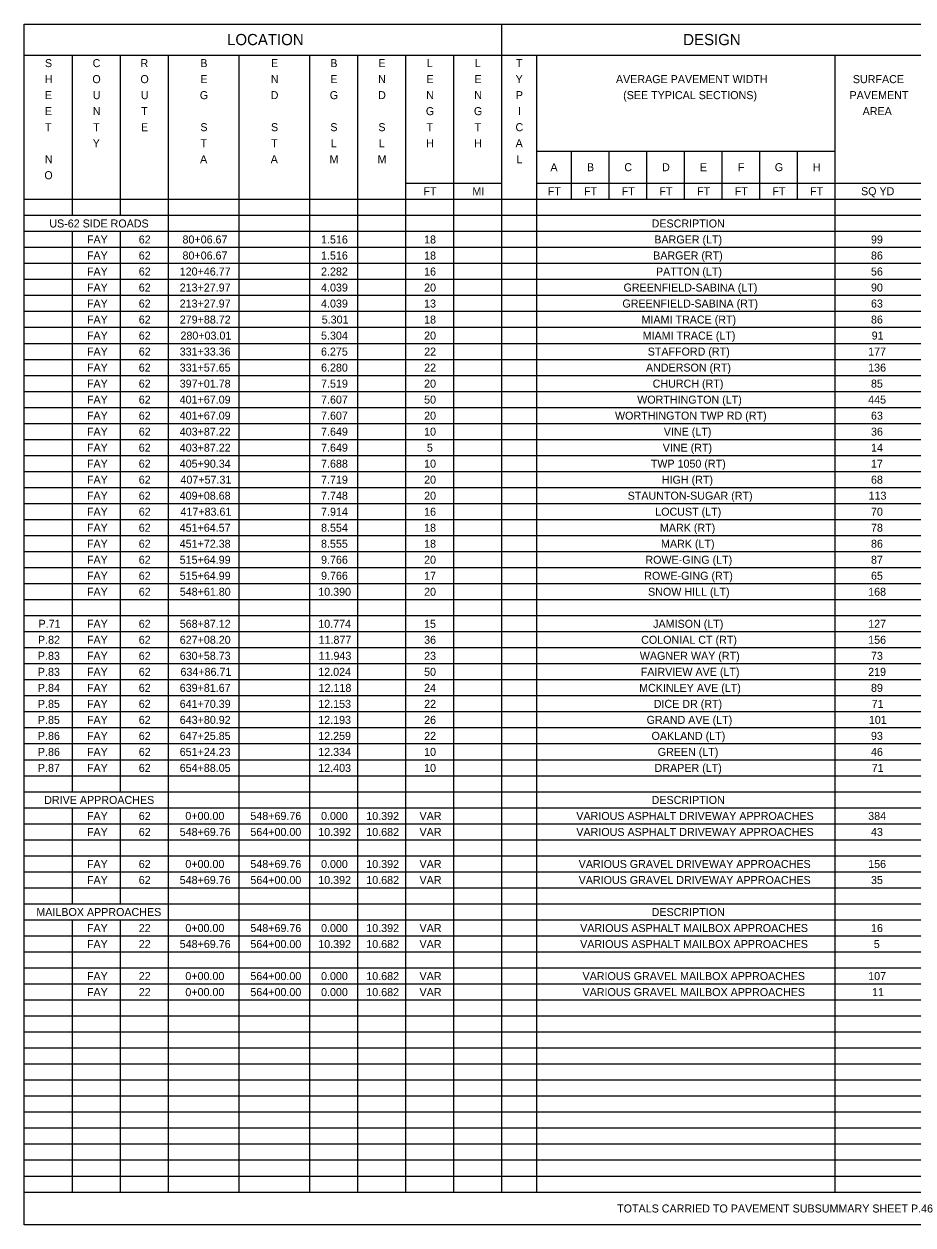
# Model space of a CAD drawing. Extents: x 12522 to 13018, y 1124 to 1902.
# Drawn here: x 12797.22 to 12812.77, y 1732.23 to 1753.23 of the extents above; entities that cross this region are included whole.
import ezdxf

# ---------------------------------------------------------------- set-up
doc = ezdxf.new("R2010")
doc.units = 0
for name, color, linetype in [('SC_Scratch1', 7, 'Continuous'), ('SH_Data', 7, 'Continuous'), ('SH_Text', 7, 'Continuous')]:
    doc.layers.add(name, color=color, linetype=linetype)

msp = doc.modelspace()

# ---------------------------------------------------------------- linework, layer by layer
at = {"layer": 'SC_Scratch1'}
msp.add_lwpolyline([(12797.224, 1753.227), (12827.724, 1753.227), (12827.724, 1732.227), (12797.224, 1732.227)], close=True, dxfattribs=at)
at = {"layer": 'SH_Data'}
for p, q in [((12805.575, 1753.227), (12805.575, 1732.803)), ((12797.224, 1752.683), (12827.678, 1752.683)), ((12798.064, 1752.683), (12798.064, 1749.883)), ((12798.904, 1752.683), (12798.904, 1749.883)), ((12799.744, 1752.683), (12799.744, 1732.803)), ((12800.979, 1752.683), (12800.979, 1732.803)), ((12802.215, 1752.683), (12802.215, 1732.803)), ((12803.055, 1752.683), (12803.055, 1732.803)), ((12803.895, 1752.683), (12803.895, 1732.803)), ((12804.735, 1752.683), (12804.735, 1732.803)), ((12806.184, 1752.683), (12806.184, 1732.803)), ((12811.405, 1752.683), (12811.405, 1732.803)), ((12806.184, 1751.003), (12811.405, 1751.003)), ((12806.794, 1751.003), (12806.794, 1750.163)), ((12807.452, 1751.003), (12807.452, 1750.163)), ((12808.111, 1751.003), (12808.111, 1750.163)), ((12808.77, 1751.003), (12808.77, 1750.163)), ((12809.429, 1751.003), (12809.429, 1750.163)), ((12810.088, 1751.003), (12810.088, 1750.163)), ((12810.747, 1751.003), (12810.747, 1750.163)), ((12803.895, 1750.443), (12805.575, 1750.443)), ((12806.184, 1750.443), (12827.678, 1750.443)), ((12797.224, 1750.163), (12827.678, 1750.163)), ((12797.224, 1749.883), (12827.678, 1749.883)), ((12797.224, 1749.603), (12827.678, 1749.603)), ((12798.064, 1749.603), (12798.064, 1739.803)), ((12798.904, 1749.603), (12798.904, 1739.803)), ((12797.224, 1749.323), (12827.678, 1749.323)), ((12797.224, 1749.043), (12827.678, 1749.043)), ((12797.224, 1748.763), (12827.678, 1748.763)), ((12797.224, 1748.483), (12827.678, 1748.483)), ((12797.224, 1748.203), (12827.678, 1748.203)), ((12797.224, 1747.923), (12827.678, 1747.923)), ((12797.224, 1747.643), (12827.678, 1747.643)), ((12797.224, 1747.363), (12827.678, 1747.363)), ((12797.224, 1747.083), (12827.678, 1747.083)), ((12797.224, 1746.803), (12827.678, 1746.803)), ((12797.224, 1746.523), (12827.678, 1746.523)), ((12797.224, 1746.243), (12827.678, 1746.243)), ((12797.224, 1745.963), (12827.678, 1745.963)), ((12797.224, 1745.683), (12827.678, 1745.683)), ((12797.224, 1745.403), (12827.678, 1745.403)), ((12797.224, 1745.123), (12827.678, 1745.123)), ((12797.224, 1744.843), (12827.678, 1744.843)), ((12797.224, 1744.563), (12827.678, 1744.563)), ((12797.224, 1744.283), (12827.678, 1744.283)), ((12797.224, 1744.003), (12827.678, 1744.003)), ((12797.224, 1743.723), (12827.678, 1743.723)), ((12797.224, 1743.443), (12827.678, 1743.443)), ((12797.224, 1743.163), (12827.678, 1743.163)), ((12797.224, 1742.883), (12827.678, 1742.883)), ((12797.224, 1742.603), (12827.678, 1742.603)), ((12797.224, 1742.323), (12827.678, 1742.323)), ((12797.224, 1742.043), (12827.678, 1742.043)), ((12797.224, 1741.763), (12827.678, 1741.763)), ((12797.224, 1741.483), (12827.678, 1741.483)), ((12797.224, 1741.203), (12827.678, 1741.203)), ((12797.224, 1740.923), (12827.678, 1740.923)), ((12797.224, 1740.643), (12827.678, 1740.643)), ((12797.224, 1740.363), (12827.678, 1740.363)), ((12797.224, 1740.083), (12827.678, 1740.083)), ((12797.224, 1739.803), (12827.678, 1739.803)), ((12797.224, 1739.523), (12827.678, 1739.523)), ((12798.064, 1739.523), (12798.064, 1737.843)), ((12798.904, 1739.523), (12798.904, 1737.843)), ((12797.224, 1739.243), (12827.678, 1739.243)), ((12797.224, 1738.963), (12827.678, 1738.963)), ((12797.224, 1738.683), (12827.678, 1738.683)), ((12797.224, 1738.403), (12827.678, 1738.403)), ((12797.224, 1738.123), (12827.678, 1738.123)), ((12797.224, 1737.843), (12827.678, 1737.843)), ((12797.224, 1737.563), (12827.678, 1737.563)), ((12798.064, 1737.563), (12798.064, 1732.803)), ((12798.904, 1737.563), (12798.904, 1732.803)), ((12797.224, 1737.283), (12827.678, 1737.283)), ((12797.224, 1737.003), (12827.678, 1737.003)), ((12797.224, 1736.723), (12827.678, 1736.723)), ((12797.224, 1736.443), (12827.678, 1736.443)), ((12797.224, 1736.163), (12827.678, 1736.163)), ((12797.224, 1735.883), (12827.678, 1735.883)), ((12797.224, 1735.603), (12827.678, 1735.603)), ((12797.224, 1735.323), (12827.678, 1735.323)), ((12797.224, 1735.043), (12827.678, 1735.043)), ((12797.224, 1734.763), (12827.678, 1734.763)), ((12797.224, 1734.483), (12827.678, 1734.483)), ((12797.224, 1734.203), (12827.678, 1734.203)), ((12797.224, 1733.923), (12827.678, 1733.923)), ((12797.224, 1733.643), (12827.678, 1733.643)), ((12797.224, 1733.363), (12827.678, 1733.363)), ((12797.224, 1733.083), (12827.678, 1733.083)), ((12797.224, 1732.803), (12827.678, 1732.803))]:
    msp.add_line(p, q, dxfattribs=at)

# ---------------------------------------------------------------- texts
at = {"layer": 'SH_Text'}
for s, height, p in [('LOCATION', 0.196, (12800.775, 1752.857)), ('DESIGN', 0.196, (12808.752, 1752.857)), ('S', 0.14, (12797.59, 1752.473)), ('C', 0.14, (12798.424, 1752.473)), ('R', 0.14, (12799.262, 1752.473)), ('B', 0.14, (12800.308, 1752.473)), ('E', 0.14, (12801.543, 1752.473)), ('B', 0.14, (12802.581, 1752.473)), ('E', 0.14, (12803.421, 1752.473)), ('L', 0.14, (12804.269, 1752.473)), ('L', 0.14, (12805.109, 1752.473)), ('T', 0.14, (12805.827, 1752.473)), ('H', 0.14, (12797.588, 1752.193)), ('O', 0.14, (12798.42, 1752.193)), ('O', 0.14, (12799.26, 1752.193)), ('E', 0.14, (12800.308, 1752.193)), ('N', 0.14, (12801.541, 1752.193)), ('E', 0.14, (12802.581, 1752.193)), ('N', 0.14, (12803.418, 1752.193)), ('E', 0.14, (12804.261, 1752.193)), ('E', 0.14, (12805.101, 1752.193)), ('Y', 0.14, (12805.821, 1752.193)), ('AVERAGE PAVEMENT WIDTH', 0.14, (12807.576, 1752.193)), ('SURFACE', 0.14, (12811.719, 1752.193)), ('E', 0.14, (12797.59, 1751.913)), ('U', 0.14, (12798.428, 1751.913)), ('U', 0.14, (12799.268, 1751.913)), ('G', 0.14, (12800.299, 1751.913)), ('D', 0.14, (12801.538, 1751.913)), ('G', 0.14, (12802.572, 1751.913)), ('D', 0.14, (12803.416, 1751.913)), ('N', 0.14, (12804.258, 1751.913)), ('N', 0.14, (12805.098, 1751.913)), ('P', 0.14, (12805.825, 1751.913)), ('(SEE TYPICAL SECTIONS)', 0.14, (12807.702, 1751.913)), ('PAVEMENT', 0.14, (12811.661, 1751.913)), ('E', 0.14, (12797.59, 1751.633)), ('N', 0.14, (12798.428, 1751.633)), ('T', 0.14, (12799.272, 1751.633)), ('G', 0.14, (12804.252, 1751.633)), ('G', 0.14, (12805.092, 1751.633)), ('I', 0.14, (12805.863, 1751.633)), ('AREA', 0.14, (12811.89, 1751.633)), ('T', 0.14, (12797.592, 1751.353)), ('T', 0.14, (12798.432, 1751.353)), ('E', 0.14, (12799.27, 1751.353)), ('S', 0.14, (12800.308, 1751.353)), ('S', 0.14, (12801.543, 1751.353)), ('S', 0.14, (12802.581, 1751.353)), ('S', 0.14, (12803.421, 1751.353)), ('T', 0.14, (12804.263, 1751.353)), ('T', 0.14, (12805.103, 1751.353)), ('C', 0.14, (12805.819, 1751.353)), ('Y', 0.14, (12798.426, 1751.073)), ('T', 0.14, (12800.31, 1751.073)), ('T', 0.14, (12801.545, 1751.073)), ('L', 0.14, (12802.589, 1751.073)), ('L', 0.14, (12803.429, 1751.073)), ('H', 0.14, (12804.258, 1751.073)), ('H', 0.14, (12805.098, 1751.073)), ('A', 0.14, (12805.821, 1751.073)), ('N', 0.14, (12797.588, 1750.793)), ('A', 0.14, (12800.303, 1750.793)), ('A', 0.14, (12801.538, 1750.793)), ('M', 0.14, (12802.568, 1750.793)), ('M', 0.14, (12803.408, 1750.793)), ('L', 0.14, (12805.834, 1750.793)), ('A', 0.14, (12806.43, 1750.653)), ('B', 0.14, (12807.069, 1750.653)), ('C', 0.14, (12807.722, 1750.653)), ('D', 0.14, (12808.382, 1750.653)), ('E', 0.14, (12809.045, 1750.653)), ('F', 0.14, (12809.709, 1750.653)), ('G', 0.14, (12810.354, 1750.653)), ('H', 0.14, (12811.02, 1750.653)), ('O', 0.14, (12797.58, 1750.513)), ('FT', 0.14, (12804.209, 1750.233)), ('MI', 0.14, (12805.065, 1750.233)), ('FT', 0.14, (12806.383, 1750.233)), ('FT', 0.14, (12807.017, 1750.233)), ('FT', 0.14, (12807.676, 1750.233)), ('FT', 0.14, (12808.335, 1750.233)), ('FT', 0.14, (12808.994, 1750.233)), ('FT', 0.14, (12809.653, 1750.233)), ('FT', 0.14, (12810.311, 1750.233)), ('FT', 0.14, (12810.97, 1750.233)), ('SQ YD', 0.14, (12811.862, 1750.233)), ('US-62 SIDE ROADS', 0.14, (12797.667, 1749.669)), ('DESCRIPTION', 0.14, (12808.2, 1749.669)), ('FAY', 0.14, (12798.325, 1749.389)), ('62', 0.14, (12799.231, 1749.389)), ('80+06.67', 0.14, (12799.996, 1749.389)), ('1.516', 0.14, (12802.419, 1749.389)), ('18', 0.14, (12804.221, 1749.389)), ('BARGER (LT)', 0.14, (12808.247, 1749.389)), ('99', 0.14, (12812.036, 1749.389)), ('FAY', 0.14, (12798.325, 1749.109)), ('62', 0.14, (12799.231, 1749.109)), ('80+06.67', 0.14, (12799.996, 1749.109)), ('1.516', 0.14, (12802.419, 1749.109)), ('18', 0.14, (12804.221, 1749.109)), ('BARGER (RT)', 0.14, (12808.227, 1749.109)), ('86', 0.14, (12812.036, 1749.109)), ('FAY', 0.14, (12798.325, 1748.829)), ('62', 0.14, (12799.231, 1748.829)), ('120+46.77', 0.14, (12799.947, 1748.829)), ('2.282', 0.14, (12802.419, 1748.829)), ('16', 0.14, (12804.221, 1748.829)), ('PATTON (LT)', 0.14, (12808.276, 1748.829)), ('56', 0.14, (12812.036, 1748.829)), ('FAY', 0.14, (12798.325, 1748.549)), ('62', 0.14, (12799.231, 1748.549)), ('213+27.97', 0.14, (12799.947, 1748.549)), ('4.039', 0.14, (12802.419, 1748.549)), ('20', 0.14, (12804.221, 1748.549)), ('GREENFIELD-SABINA (LT)', 0.14, (12807.709, 1748.549)), ('90', 0.14, (12812.036, 1748.549)), ('FAY', 0.14, (12798.325, 1748.269)), ('62', 0.14, (12799.231, 1748.269)), ('213+27.97', 0.14, (12799.947, 1748.269)), ('4.039', 0.14, (12802.419, 1748.269)), ('13', 0.14, (12804.221, 1748.269)), ('GREENFIELD-SABINA (RT)', 0.14, (12807.689, 1748.269)), ('63', 0.14, (12812.036, 1748.269)), ('FAY', 0.14, (12798.325, 1747.989)), ('62', 0.14, (12799.231, 1747.989)), ('279+88.72', 0.14, (12799.948, 1747.989)), ('5.301', 0.14, (12802.431, 1747.989)), ('18', 0.14, (12804.221, 1747.989)), ('MIAMI TRACE (RT)', 0.14, (12808.024, 1747.989)), ('86', 0.14, (12812.036, 1747.989)), ('FAY', 0.14, (12798.325, 1747.709)), ('62', 0.14, (12799.231, 1747.709)), ('280+03.01', 0.14, (12799.96, 1747.709)), ('5.304', 0.14, (12802.419, 1747.709)), ('20', 0.14, (12804.221, 1747.709)), ('MIAMI TRACE (LT)', 0.14, (12808.043, 1747.709)), ('91', 0.14, (12812.048, 1747.709)), ('FAY', 0.14, (12798.325, 1747.429)), ('62', 0.14, (12799.231, 1747.429)), ('331+33.36', 0.14, (12799.947, 1747.429)), ('6.275', 0.14, (12802.418, 1747.429)), ('22', 0.14, (12804.222, 1747.429)), ('STAFFORD (RT)', 0.14, (12808.131, 1747.429)), ('177', 0.14, (12811.987, 1747.429)), ('FAY', 0.14, (12798.325, 1747.149)), ('62', 0.14, (12799.231, 1747.149)), ('331+57.65', 0.14, (12799.947, 1747.149)), ('6.280', 0.14, (12802.419, 1747.149)), ('22', 0.14, (12804.222, 1747.149)), ('ANDERSON (RT)', 0.14, (12808.1, 1747.149)), ('136', 0.14, (12811.987, 1747.149)), ('FAY', 0.14, (12798.325, 1746.869)), ('62', 0.14, (12799.231, 1746.869)), ('397+01.78', 0.14, (12799.947, 1746.869)), ('7.519', 0.14, (12802.419, 1746.869)), ('20', 0.14, (12804.221, 1746.869)), ('CHURCH (RT)', 0.14, (12808.218, 1746.869)), ('85', 0.14, (12812.036, 1746.869)), ('FAY', 0.14, (12798.325, 1746.589)), ('62', 0.14, (12799.231, 1746.589)), ('401+67.09', 0.14, (12799.947, 1746.589)), ('7.607', 0.14, (12802.419, 1746.589)), ('50', 0.14, (12804.221, 1746.589)), ('WORTHINGTON (LT)', 0.14, (12807.947, 1746.589)), ('445', 0.14, (12811.987, 1746.589)), ('FAY', 0.14, (12798.325, 1746.309)), ('62', 0.14, (12799.231, 1746.309)), ('401+67.09', 0.14, (12799.947, 1746.309)), ('7.607', 0.14, (12802.419, 1746.309)), ('20', 0.14, (12804.221, 1746.309)), ('WORTHINGTON TWP RD (RT)', 0.14, (12807.559, 1746.309)), ('63', 0.14, (12812.036, 1746.309)), ('FAY', 0.14, (12798.325, 1746.029)), ('62', 0.14, (12799.231, 1746.029)), ('403+87.22', 0.14, (12799.948, 1746.029)), ('7.649', 0.14, (12802.419, 1746.029)), ('10', 0.14, (12804.221, 1746.029)), ('VINE (LT)', 0.14, (12808.413, 1746.029)), ('36', 0.14, (12812.036, 1746.029)), ('FAY', 0.14, (12798.325, 1745.749)), ('62', 0.14, (12799.231, 1745.749)), ('403+87.22', 0.14, (12799.948, 1745.749)), ('7.649', 0.14, (12802.419, 1745.749)), ('5', 0.14, (12804.269, 1745.749)), ('VINE (RT)', 0.14, (12808.394, 1745.749)), ('14', 0.14, (12812.037, 1745.749)), ('FAY', 0.14, (12798.325, 1745.469)), ('62', 0.14, (12799.231, 1745.469)), ('405+90.34', 0.14, (12799.948, 1745.469)), ('7.688', 0.14, (12802.419, 1745.469)), ('10', 0.14, (12804.221, 1745.469)), ('TWP 1050 (RT)', 0.14, (12808.185, 1745.469)), ('17', 0.14, (12812.036, 1745.469)), ('FAY', 0.14, (12798.325, 1745.189)), ('62', 0.14, (12799.231, 1745.189)), ('407+57.31', 0.14, (12799.96, 1745.189)), ('7.719', 0.14, (12802.419, 1745.189)), ('20', 0.14, (12804.221, 1745.189)), ('HIGH (RT)', 0.14, (12808.379, 1745.189)), ('68', 0.14, (12812.036, 1745.189)), ('FAY', 0.14, (12798.325, 1744.909)), ('62', 0.14, (12799.231, 1744.909)), ('409+08.68', 0.14, (12799.947, 1744.909)), ('7.748', 0.14, (12802.419, 1744.909)), ('20', 0.14, (12804.221, 1744.909)), ('STAUNTON-SUGAR (RT)', 0.14, (12807.781, 1744.909)), ('113', 0.14, (12811.994, 1744.909)), ('FAY', 0.14, (12798.325, 1744.629)), ('62', 0.14, (12799.231, 1744.629)), ('417+83.61', 0.14, (12799.96, 1744.629)), ('7.914', 0.14, (12802.419, 1744.629)), ('16', 0.14, (12804.221, 1744.629)), ('LOCUST (LT)', 0.14, (12808.263, 1744.629)), ('70', 0.14, (12812.036, 1744.629)), ('FAY', 0.14, (12798.325, 1744.349)), ('62', 0.14, (12799.231, 1744.349)), ('451+64.57', 0.14, (12799.947, 1744.349)), ('8.554', 0.14, (12802.419, 1744.349)), ('18', 0.14, (12804.221, 1744.349)), ('MARK (RT)', 0.14, (12808.345, 1744.349)), ('78', 0.14, (12812.036, 1744.349)), ('FAY', 0.14, (12798.325, 1744.069)), ('62', 0.14, (12799.231, 1744.069)), ('451+72.38', 0.14, (12799.947, 1744.069)), ('8.555', 0.14, (12802.418, 1744.069)), ('18', 0.14, (12804.221, 1744.069)), ('MARK (LT)', 0.14, (12808.364, 1744.069)), ('86', 0.14, (12812.036, 1744.069)), ('FAY', 0.14, (12798.325, 1743.789)), ('62', 0.14, (12799.231, 1743.789)), ('515+64.99', 0.14, (12799.947, 1743.789)), ('9.766', 0.14, (12802.419, 1743.789)), ('20', 0.14, (12804.221, 1743.789)), ('ROWE-GING (LT)', 0.14, (12808.091, 1743.789)), ('87', 0.14, (12812.036, 1743.789)), ('FAY', 0.14, (12798.325, 1743.509)), ('62', 0.14, (12799.231, 1743.509)), ('515+64.99', 0.14, (12799.947, 1743.509)), ('9.766', 0.14, (12802.419, 1743.509)), ('17', 0.14, (12804.221, 1743.509)), ('ROWE-GING (RT)', 0.14, (12808.071, 1743.509)), ('65', 0.14, (12812.036, 1743.509)), ('FAY', 0.14, (12798.325, 1743.229)), ('62', 0.14, (12799.231, 1743.229)), ('548+61.80', 0.14, (12799.948, 1743.229)), ('10.390', 0.14, (12802.37, 1743.229)), ('20', 0.14, (12804.221, 1743.229)), ('SNOW HILL (LT)', 0.14, (12808.138, 1743.229)), ('168', 0.14, (12811.987, 1743.229)), ('P.71', 0.14, (12797.479, 1742.669)), ('FAY', 0.14, (12798.325, 1742.669)), ('62', 0.14, (12799.231, 1742.669)), ('568+87.12', 0.14, (12799.948, 1742.669)), ('10.774', 0.14, (12802.37, 1742.669)), ('15', 0.14, (12804.22, 1742.669)), ('JAMISON (LT)', 0.14, (12808.227, 1742.669)), ('127', 0.14, (12811.987, 1742.669)), ('P.82', 0.14, (12797.468, 1742.389)), ('FAY', 0.14, (12798.325, 1742.389)), ('62', 0.14, (12799.231, 1742.389)), ('627+08.20', 0.14, (12799.948, 1742.389)), ('11.877', 0.14, (12802.376, 1742.389)), ('36', 0.14, (12804.221, 1742.389)), ('COLONIAL CT (RT)', 0.14, (12808.017, 1742.389)), ('156', 0.14, (12811.987, 1742.389)), ('P.83', 0.14, (12797.467, 1742.109)), ('FAY', 0.14, (12798.325, 1742.109)), ('62', 0.14, (12799.231, 1742.109)), ('630+58.73', 0.14, (12799.947, 1742.109)), ('11.943', 0.14, (12802.376, 1742.109)), ('23', 0.14, (12804.221, 1742.109)), ('WAGNER WAY (RT)', 0.14, (12807.993, 1742.109)), ('73', 0.14, (12812.036, 1742.109)), ('P.83', 0.14, (12797.467, 1741.829)), ('FAY', 0.14, (12798.325, 1741.829)), ('62', 0.14, (12799.231, 1741.829)), ('634+86.71', 0.14, (12799.96, 1741.829)), ('12.024', 0.14, (12802.37, 1741.829)), ('50', 0.14, (12804.221, 1741.829)), ('FAIRVIEW AVE (LT)', 0.14, (12808.01, 1741.829)), ('219', 0.14, (12811.987, 1741.829)), ('P.84', 0.14, (12797.467, 1741.549)), ('FAY', 0.14, (12798.325, 1741.549)), ('62', 0.14, (12799.231, 1741.549)), ('639+81.67', 0.14, (12799.947, 1741.549)), ('12.118', 0.14, (12802.376, 1741.549)), ('24', 0.14, (12804.221, 1741.549)), ('MCKINLEY AVE (LT)', 0.14, (12807.981, 1741.549)), ('89', 0.14, (12812.036, 1741.549)), ('P.85', 0.14, (12797.467, 1741.269)), ('FAY', 0.14, (12798.325, 1741.269)), ('62', 0.14, (12799.231, 1741.269)), ('641+70.39', 0.14, (12799.947, 1741.269)), ('12.153', 0.14, (12802.37, 1741.269)), ('22', 0.14, (12804.222, 1741.269)), ('DICE DR (RT)', 0.14, (12808.237, 1741.269)), ('71', 0.14, (12812.048, 1741.269)), ('P.85', 0.14, (12797.467, 1740.989)), ('FAY', 0.14, (12798.325, 1740.989)), ('62', 0.14, (12799.231, 1740.989)), ('643+80.92', 0.14, (12799.948, 1740.989)), ('12.193', 0.14, (12802.37, 1740.989)), ('26', 0.14, (12804.221, 1740.989)), ('GRAND AVE (LT)', 0.14, (12808.112, 1740.989)), ('101', 0.14, (12811.999, 1740.989)), ('P.86', 0.14, (12797.467, 1740.709)), ('FAY', 0.14, (12798.325, 1740.709)), ('62', 0.14, (12799.231, 1740.709)), ('647+25.85', 0.14, (12799.947, 1740.709)), ('12.259', 0.14, (12802.37, 1740.709)), ('22', 0.14, (12804.222, 1740.709)), ('OAKLAND (LT)', 0.14, (12808.198, 1740.709)), ('93', 0.14, (12812.036, 1740.709)), ('P.86', 0.14, (12797.467, 1740.429)), ('FAY', 0.14, (12798.325, 1740.429)), ('62', 0.14, (12799.231, 1740.429)), ('651+24.23', 0.14, (12799.947, 1740.429)), ('12.334', 0.14, (12802.37, 1740.429)), ('10', 0.14, (12804.221, 1740.429)), ('GREEN (LT)', 0.14, (12808.306, 1740.429)), ('46', 0.14, (12812.036, 1740.429)), ('P.87', 0.14, (12797.467, 1740.149)), ('FAY', 0.14, (12798.325, 1740.149)), ('62', 0.14, (12799.231, 1740.149)), ('654+88.05', 0.14, (12799.947, 1740.149)), ('12.403', 0.14, (12802.37, 1740.149)), ('10', 0.14, (12804.221, 1740.149)), ('DRAPER (LT)', 0.14, (12808.252, 1740.149)), ('71', 0.14, (12812.048, 1740.149)), ('DRIVE APPROACHES', 0.14, (12797.577, 1739.589)), ('DESCRIPTION', 0.14, (12808.2, 1739.589)), ('FAY', 0.14, (12798.325, 1739.309)), ('62', 0.14, (12799.231, 1739.309)), ('0+00.00', 0.14, (12800.046, 1739.309)), ('548+69.76', 0.14, (12801.183, 1739.309)), ('0.000', 0.14, (12802.419, 1739.309)), ('10.392', 0.14, (12803.21, 1739.309)), ('VAR', 0.14, (12804.141, 1739.309)), ('VARIOUS ASPHALT DRIVEWAY APPROACHES', 0.14, (12806.883, 1739.309)), ('384', 0.14, (12811.988, 1739.309)), ('FAY', 0.14, (12798.325, 1739.029)), ('62', 0.14, (12799.231, 1739.029)), ('548+69.76', 0.14, (12799.947, 1739.029)), ('564+00.00', 0.14, (12801.183, 1739.029)), ('10.392', 0.14, (12802.37, 1739.029)), ('10.682', 0.14, (12803.21, 1739.029)), ('VAR', 0.14, (12804.141, 1739.029)), ('VARIOUS ASPHALT DRIVEWAY APPROACHES', 0.14, (12806.883, 1739.029)), ('43', 0.14, (12812.036, 1739.029)), ('FAY', 0.14, (12798.325, 1738.469)), ('62', 0.14, (12799.231, 1738.469)), ('0+00.00', 0.14, (12800.046, 1738.469)), ('548+69.76', 0.14, (12801.183, 1738.469)), ('0.000', 0.14, (12802.419, 1738.469)), ('10.392', 0.14, (12803.21, 1738.469)), ('VAR', 0.14, (12804.141, 1738.469)), ('VARIOUS GRAVEL DRIVEWAY APPROACHES', 0.14, (12806.924, 1738.469)), ('156', 0.14, (12811.987, 1738.469)), ('FAY', 0.14, (12798.325, 1738.189)), ('62', 0.14, (12799.231, 1738.189)), ('548+69.76', 0.14, (12799.947, 1738.189)), ('564+00.00', 0.14, (12801.183, 1738.189)), ('10.392', 0.14, (12802.37, 1738.189)), ('10.682', 0.14, (12803.21, 1738.189)), ('VAR', 0.14, (12804.141, 1738.189)), ('VARIOUS GRAVEL DRIVEWAY APPROACHES', 0.14, (12806.924, 1738.189)), ('35', 0.14, (12812.036, 1738.189)), ('MAILBOX APPROACHES', 0.14, (12797.44, 1737.629)), ('DESCRIPTION', 0.14, (12808.2, 1737.629)), ('FAY', 0.14, (12798.325, 1737.349)), ('22', 0.14, (12799.231, 1737.349)), ('0+00.00', 0.14, (12800.046, 1737.349)), ('548+69.76', 0.14, (12801.183, 1737.349)), ('0.000', 0.14, (12802.419, 1737.349)), ('10.392', 0.14, (12803.21, 1737.349)), ('VAR', 0.14, (12804.141, 1737.349)), ('VARIOUS ASPHALT MAILBOX APPROACHES', 0.14, (12806.95, 1737.349)), ('16', 0.14, (12812.036, 1737.349)), ('FAY', 0.14, (12798.325, 1737.069)), ('22', 0.14, (12799.231, 1737.069)), ('548+69.76', 0.14, (12799.947, 1737.069)), ('564+00.00', 0.14, (12801.183, 1737.069)), ('10.392', 0.14, (12802.37, 1737.069)), ('10.682', 0.14, (12803.21, 1737.069)), ('VAR', 0.14, (12804.141, 1737.069)), ('VARIOUS ASPHALT MAILBOX APPROACHES', 0.14, (12806.95, 1737.069)), ('5', 0.14, (12812.085, 1737.069)), ('FAY', 0.14, (12798.325, 1736.509)), ('22', 0.14, (12799.231, 1736.509)), ('0+00.00', 0.14, (12800.046, 1736.509)), ('564+00.00', 0.14, (12801.183, 1736.509)), ('0.000', 0.14, (12802.419, 1736.509)), ('10.682', 0.14, (12803.21, 1736.509)), ('VAR', 0.14, (12804.141, 1736.509)), ('VARIOUS GRAVEL MAILBOX APPROACHES', 0.14, (12806.991, 1736.509)), ('107', 0.14, (12811.987, 1736.509)), ('FAY', 0.14, (12798.325, 1736.229)), ('22', 0.14, (12799.231, 1736.229)), ('0+00.00', 0.14, (12800.046, 1736.229)), ('564+00.00', 0.14, (12801.183, 1736.229)), ('0.000', 0.14, (12802.419, 1736.229)), ('10.682', 0.14, (12803.21, 1736.229)), ('VAR', 0.14, (12804.141, 1736.229)), ('VARIOUS GRAVEL MAILBOX APPROACHES', 0.14, (12806.991, 1736.229)), ('11', 0.14, (12812.055, 1736.229)), ('TOTALS CARRIED TO PAVEMENT SUBSUMMARY SHEET P.46', 0.14, (12807.597, 1732.445))]:
    msp.add_text(s, height=height, dxfattribs=at).set_placement(p)

doc.saveas('drawing.dxf')
